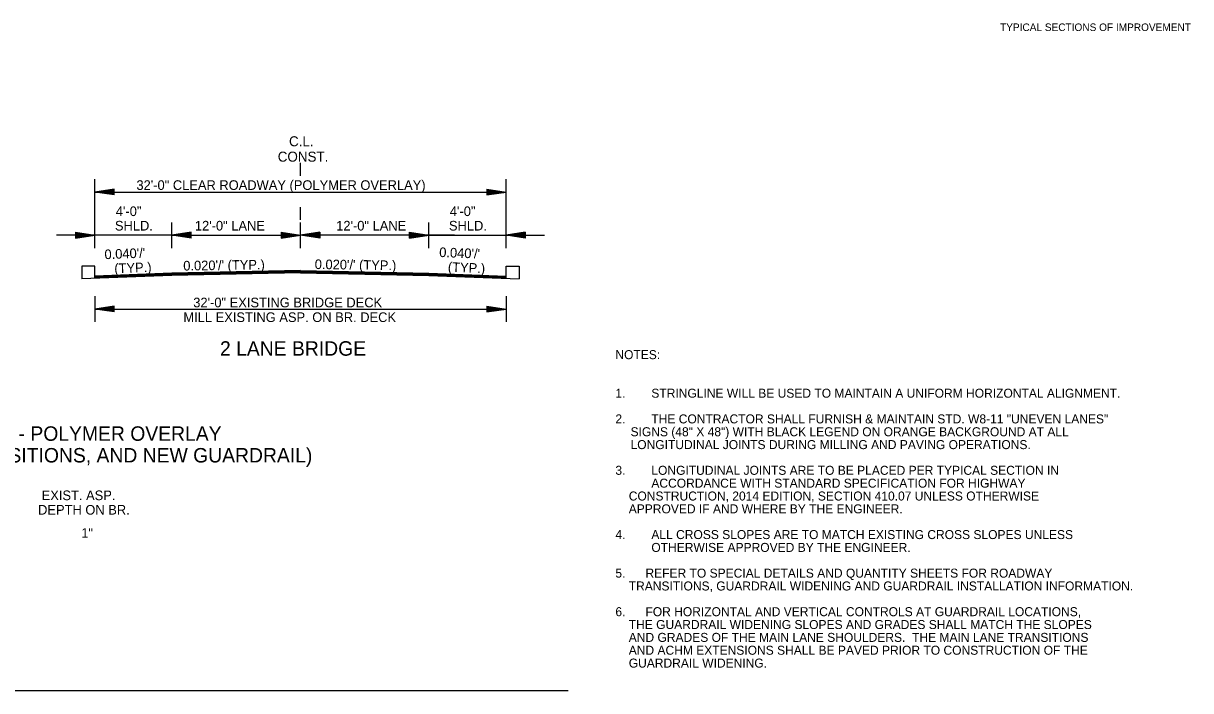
# Model space of a CAD drawing. Extents: x 545241 to 1930787, y -1971772 to 596640.
# Drawn here: x 547347 to 548255, y -1960905 to -1960386 of the extents above; entities that cross this region are included whole.
import ezdxf

# ---------------------------------------------------------------- set-up
doc = ezdxf.new("R2010")
doc.units = 0
for name, color, linetype in [('R_Border', 7, 'Continuous'), ('R_Border Notes', 7, 'Continuous'), ('R_Border Prem', 7, 'Continuous'), ('R_Draft', 7, 'Continuous')]:
    doc.layers.add(name, color=color, linetype=linetype)

msp = doc.modelspace()

# ---------------------------------------------------------------- linework, layer by layer
at = {"layer": 'R_Border'}
for p, q in [((547402.22, -1960550.83), (547372.22, -1960550.83)), ((547722.22, -1960550.83), (547752.22, -1960550.83)), ((547402.22, -1960574.9), (547392.05, -1960574.9)), ((547392.05, -1960574.9), (547392.05, -1960584.91)), ((547402.22, -1960584.51), (547402.22, -1960574.9)), ((547722.22, -1960574.93), (547732.39, -1960574.93)), ((547722.22, -1960584.34), (547722.22, -1960574.93)), ((547732.39, -1960574.93), (547732.39, -1960584.74)), ((546742.77, -1960905.24), (547770.72, -1960905.24))]:
    msp.add_line(p, q, dxfattribs=at)
at = {"layer": 'R_Draft'}
for p, q in [((547562.22, -1960504.57), (547562.22, -1960494.57)), ((547402.22, -1960560.83), (547402.22, -1960507.29)), ((547722.22, -1960560.83), (547722.22, -1960507.29)), ((547417.22, -1960515.04), (547402.22, -1960517.29)), ((547417.22, -1960515.42), (547404.72, -1960517.29)), ((547417.22, -1960515.8), (547407.3, -1960517.29)), ((547417.22, -1960516.17), (547409.8, -1960517.29)), ((547417.22, -1960516.56), (547412.34, -1960517.29)), ((547417.22, -1960519.54), (547417.22, -1960515.04)), ((547707.22, -1960515.04), (547722.22, -1960517.29)), ((547707.22, -1960515.04), (547707.22, -1960519.54)), ((547707.22, -1960515.42), (547719.71, -1960517.29)), ((547707.22, -1960515.8), (547717.13, -1960517.29)), ((547707.22, -1960516.17), (547714.64, -1960517.29)), ((547707.22, -1960516.56), (547712.09, -1960517.29)), ((547402.22, -1960517.29), (547722.22, -1960517.29)), ((547417.22, -1960519.54), (547402.22, -1960517.29)), ((547417.22, -1960519.17), (547404.72, -1960517.29)), ((547417.22, -1960518.78), (547407.3, -1960517.29)), ((547417.22, -1960518.41), (547409.8, -1960517.29)), ((547417.22, -1960518.02), (547412.34, -1960517.29)), ((547417.22, -1960516.94), (547414.85, -1960517.29)), ((547417.22, -1960517.64), (547414.85, -1960517.29)), ((547707.22, -1960516.94), (547709.59, -1960517.29)), ((547707.22, -1960519.54), (547722.22, -1960517.29)), ((547707.22, -1960518.03), (547712.09, -1960517.29)), ((547707.22, -1960518.78), (547717.13, -1960517.29)), ((547707.22, -1960519.17), (547719.71, -1960517.29)), ((547707.22, -1960518.41), (547714.64, -1960517.29)), ((547707.22, -1960517.64), (547709.59, -1960517.29)), ((547562.22, -1960538.81), (547562.22, -1960528.94)), ((547462.22, -1960560.83), (547462.22, -1960540.94)), ((547562.22, -1960560.83), (547562.22, -1960540.94)), ((547662.22, -1960560.83), (547662.22, -1960540.94)), ((547387.22, -1960548.58), (547402.22, -1960550.83)), ((547387.22, -1960548.58), (547387.22, -1960553.08)), ((547387.22, -1960548.95), (547399.71, -1960550.83)), ((547387.22, -1960549.34), (547397.13, -1960550.83)), ((547387.22, -1960549.71), (547394.64, -1960550.83)), ((547387.22, -1960550.1), (547392.09, -1960550.83)), ((547387.22, -1960550.48), (547389.59, -1960550.83)), ((547387.22, -1960553.08), (547402.22, -1960550.83)), ((547387.22, -1960551.56), (547392.09, -1960550.83)), ((547387.22, -1960552.32), (547397.13, -1960550.83)), ((547387.22, -1960552.7), (547399.71, -1960550.83)), ((547387.22, -1960551.95), (547394.64, -1960550.83)), ((547387.22, -1960551.18), (547389.59, -1960550.83)), ((547462.22, -1960550.83), (547402.22, -1960550.83)), ((547477.22, -1960548.58), (547462.22, -1960550.83)), ((547477.22, -1960553.08), (547462.22, -1960550.83)), ((547462.22, -1960550.83), (547562.22, -1960550.83)), ((547477.22, -1960548.95), (547464.72, -1960550.83)), ((547477.22, -1960552.7), (547464.72, -1960550.83)), ((547477.22, -1960549.34), (547467.3, -1960550.83)), ((547477.22, -1960552.32), (547467.3, -1960550.83)), ((547477.22, -1960549.71), (547469.8, -1960550.83)), ((547477.22, -1960551.95), (547469.8, -1960550.83)), ((547477.22, -1960550.09), (547472.34, -1960550.83)), ((547477.22, -1960551.56), (547472.34, -1960550.83)), ((547477.22, -1960550.48), (547474.85, -1960550.83)), ((547477.22, -1960551.18), (547474.85, -1960550.83)), ((547477.22, -1960553.08), (547477.22, -1960548.58)), ((547547.22, -1960548.58), (547562.22, -1960550.83)), ((547547.22, -1960548.58), (547547.22, -1960553.08)), ((547547.22, -1960548.95), (547559.71, -1960550.83)), ((547547.22, -1960549.34), (547557.13, -1960550.83)), ((547547.22, -1960549.71), (547554.64, -1960550.83)), ((547547.22, -1960550.1), (547552.09, -1960550.83)), ((547547.22, -1960550.48), (547549.59, -1960550.83)), ((547547.22, -1960553.08), (547562.22, -1960550.83)), ((547547.22, -1960551.56), (547552.09, -1960550.83)), ((547547.22, -1960552.32), (547557.13, -1960550.83)), ((547547.22, -1960552.7), (547559.71, -1960550.83)), ((547547.22, -1960551.95), (547554.64, -1960550.83)), ((547547.22, -1960551.18), (547549.59, -1960550.83)), ((547577.22, -1960548.58), (547562.22, -1960550.83)), ((547682.22, -1960550.83), (547562.22, -1960550.83)), ((547577.22, -1960553.08), (547562.22, -1960550.83)), ((547577.22, -1960548.95), (547564.72, -1960550.83)), ((547577.22, -1960552.7), (547564.72, -1960550.83)), ((547577.22, -1960549.34), (547567.3, -1960550.83)), ((547577.22, -1960552.32), (547567.3, -1960550.83)), ((547577.22, -1960549.71), (547569.8, -1960550.83)), ((547577.22, -1960551.95), (547569.8, -1960550.83)), ((547577.22, -1960550.1), (547572.34, -1960550.83)), ((547577.22, -1960551.56), (547572.34, -1960550.83)), ((547577.22, -1960550.48), (547574.85, -1960550.83)), ((547577.22, -1960551.18), (547574.85, -1960550.83)), ((547577.22, -1960548.58), (547577.22, -1960553.08)), ((547647.22, -1960548.58), (547662.22, -1960550.83)), ((547647.22, -1960553.08), (547647.22, -1960548.58)), ((547647.22, -1960548.95), (547659.71, -1960550.83)), ((547647.22, -1960549.34), (547657.13, -1960550.83)), ((547647.22, -1960549.71), (547654.64, -1960550.83)), ((547647.22, -1960550.09), (547652.09, -1960550.83)), ((547647.22, -1960550.48), (547649.59, -1960550.83)), ((547647.22, -1960553.08), (547662.22, -1960550.83)), ((547647.22, -1960551.56), (547652.09, -1960550.83)), ((547647.22, -1960552.32), (547657.13, -1960550.83)), ((547647.22, -1960552.7), (547659.71, -1960550.83)), ((547647.22, -1960551.95), (547654.64, -1960550.83)), ((547647.22, -1960551.18), (547649.59, -1960550.83)), ((547662.22, -1960550.83), (547722.22, -1960550.83)), ((547737.22, -1960548.58), (547722.22, -1960550.83)), ((547737.22, -1960553.08), (547722.22, -1960550.83)), ((547737.22, -1960548.95), (547724.72, -1960550.83)), ((547737.22, -1960552.7), (547724.72, -1960550.83)), ((547737.22, -1960549.34), (547727.3, -1960550.83)), ((547737.22, -1960552.32), (547727.3, -1960550.83)), ((547737.22, -1960549.71), (547729.8, -1960550.83)), ((547737.22, -1960551.95), (547729.8, -1960550.83)), ((547737.22, -1960550.1), (547732.34, -1960550.83)), ((547737.22, -1960551.56), (547732.34, -1960550.83)), ((547737.22, -1960550.48), (547734.85, -1960550.83)), ((547737.22, -1960551.18), (547734.85, -1960550.83)), ((547737.22, -1960548.58), (547737.22, -1960553.08)), ((547462.22, -1960580.44), (547402.22, -1960582.84)), ((547562.22, -1960578.44), (547462.22, -1960580.44)), ((547562.22, -1960578.74), (547462.22, -1960580.74)), ((547562.23, -1960579.04), (547462.22, -1960581.04)), ((547562.24, -1960579.34), (547462.22, -1960581.34)), ((547562.24, -1960579.64), (547462.22, -1960581.64)), ((547562.25, -1960579.94), (547462.22, -1960581.94)), ((547562.25, -1960580.11), (547462.22, -1960582.11)), ((547562.19, -1960579.64), (547662.22, -1960581.64)), ((547562.19, -1960579.94), (547662.22, -1960581.94)), ((547562.19, -1960580.11), (547662.22, -1960582.11)), ((547562.2, -1960579.34), (547662.22, -1960581.34)), ((547562.21, -1960578.74), (547662.22, -1960580.74)), ((547562.21, -1960579.04), (547662.22, -1960581.04)), ((547562.22, -1960578.44), (547662.22, -1960580.44)), ((547662.22, -1960580.44), (547722.22, -1960582.84)), ((547462.22, -1960582.11), (547392.05, -1960584.91)), ((547462.22, -1960580.74), (547402.22, -1960583.14)), ((547462.22, -1960581.04), (547402.22, -1960583.44)), ((547462.22, -1960581.34), (547402.22, -1960583.74)), ((547462.22, -1960581.64), (547402.22, -1960584.04)), ((547462.22, -1960581.94), (547402.22, -1960584.34)), ((547662.22, -1960580.74), (547722.22, -1960583.14)), ((547662.22, -1960581.04), (547722.22, -1960583.44)), ((547662.22, -1960581.34), (547722.22, -1960583.74)), ((547662.22, -1960581.64), (547722.22, -1960584.04)), ((547662.22, -1960581.94), (547722.22, -1960584.34)), ((547662.22, -1960582.11), (547732.39, -1960584.91)), ((547402.22, -1960598.29), (547402.22, -1960618.29)), ((547722.22, -1960598.29), (547722.22, -1960618.29)), ((547417.22, -1960606.04), (547402.22, -1960608.29)), ((547417.22, -1960606.42), (547404.72, -1960608.29)), ((547417.22, -1960606.8), (547407.3, -1960608.29)), ((547417.22, -1960607.18), (547409.8, -1960608.29)), ((547417.22, -1960607.56), (547412.34, -1960608.29)), ((547417.22, -1960610.54), (547417.22, -1960606.04)), ((547707.22, -1960606.04), (547722.22, -1960608.29)), ((547707.22, -1960606.04), (547707.22, -1960610.54)), ((547707.22, -1960606.42), (547719.71, -1960608.29)), ((547707.22, -1960606.8), (547717.13, -1960608.29)), ((547707.22, -1960607.18), (547714.64, -1960608.29)), ((547707.22, -1960607.57), (547712.09, -1960608.29)), ((547402.22, -1960608.29), (547722.22, -1960608.29)), ((547417.22, -1960610.54), (547402.22, -1960608.29)), ((547417.22, -1960610.17), (547404.72, -1960608.29)), ((547417.22, -1960609.79), (547407.3, -1960608.29)), ((547417.22, -1960609.41), (547409.8, -1960608.29)), ((547417.22, -1960609.02), (547412.34, -1960608.29)), ((547417.22, -1960607.94), (547414.85, -1960608.29)), ((547417.22, -1960608.65), (547414.85, -1960608.29)), ((547707.22, -1960607.94), (547709.59, -1960608.29)), ((547707.22, -1960610.54), (547722.22, -1960608.29)), ((547707.22, -1960609.03), (547712.09, -1960608.29)), ((547707.22, -1960609.79), (547717.13, -1960608.29)), ((547707.22, -1960610.17), (547719.71, -1960608.29)), ((547707.22, -1960609.41), (547714.64, -1960608.29)), ((547707.22, -1960608.65), (547709.59, -1960608.29))]:
    msp.add_line(p, q, dxfattribs=at)

# ---------------------------------------------------------------- texts
at = {"layer": 'R_Border Notes'}
for s, p in [('NOTES: ', (547807.36, -1960647.3)), ('1.', (547807.36, -1960677.3)), ('STRINGLINE WILL BE USED TO MAINTAIN A UNIFORM HORIZONTAL ALIGNMENT.', (547835.36, -1960677.3)), ('2.', (547807.36, -1960697.3)), ('THE CONTRACTOR SHALL FURNISH & MAINTAIN STD. W8-11 "UNEVEN LANES" ', (547835.36, -1960697.3)), ('    SIGNS (48" X 48") WITH BLACK LEGEND ON ORANGE BACKGROUND AT ALL ', (547808.76, -1960707.3)), ('    LONGITUDINAL JOINTS DURING MILLING AND PAVING OPERATIONS.', (547808.76, -1960717.3)), ('3.', (547807.36, -1960737.3)), ('LONGITUDINAL JOINTS ARE TO BE PLACED PER TYPICAL SECTION IN ', (547835.36, -1960737.3)), ('ACCORDANCE WITH STANDARD SPECIFICATION FOR HIGHWAY', (547835.36, -1960747.3)), ('    CONSTRUCTION, 2014 EDITION, SECTION 410.07 UNLESS OTHERWISE', (547807.36, -1960757.3)), ('    APPROVED IF AND WHERE BY THE ENGINEER.', (547807.36, -1960767.3)), ('4.', (547807.36, -1960787.3)), ('ALL CROSS SLOPES ARE TO MATCH EXISTING CROSS SLOPES UNLESS ', (547835.36, -1960787.3)), ('OTHERWISE APPROVED BY THE ENGINEER.', (547835.36, -1960797.3)), ('5.      REFER TO SPECIAL DETAILS AND QUANTITY SHEETS FOR ROADWAY', (547807.36, -1960817.3)), ('    TRANSITIONS, GUARDRAIL WIDENING AND GUARDRAIL INSTALLATION INFORMATION.', (547807.36, -1960827.3)), ('6.      FOR HORIZONTAL AND VERTICAL CONTROLS AT GUARDRAIL LOCATIONS,', (547807.36, -1960847.3)), ('    THE GUARDRAIL WIDENING SLOPES AND GRADES SHALL MATCH THE SLOPES', (547807.36, -1960857.3)), ('    AND GRADES OF THE MAIN LANE SHOULDERS.  THE MAIN LANE TRANSITIONS', (547807.36, -1960867.3)), ('    AND ACHM EXTENSIONS SHALL BE PAVED PRIOR TO CONSTRUCTION OF THE', (547807.36, -1960877.3)), ('    GUARDRAIL WIDENING.', (547807.36, -1960887.3))]:
    msp.add_text(s, height=7, dxfattribs=at).set_placement(p)
at = {"layer": 'R_Border Prem'}
msp.add_text('TYPICAL SECTIONS OF IMPROVEMENT', height=5.862, rotation=360, dxfattribs=at).set_placement((548106.81, -1960391.97))
at = {"layer": 'R_Draft'}
for s, height, p in [('C.L.', 7.8, (547553.32, -1960481.68)), ('CONST.', 7.8, (547544.54, -1960493.64)), ('32\'-0" CLEAR ROADWAY (POLYMER OVERLAY)', 7.5, (547434.54, -1960515.62)), ('4\'-0" ', 7.5, (547418.49, -1960535.97)), ('4\'-0"', 7.5, (547678.49, -1960535.97)), ('SHLD.', 7.5, (547417.81, -1960547.22)), ('12\'-0" LANE', 7.5, (547480.03, -1960547.22)), ('12\'-0" LANE', 7.5, (547590.03, -1960547.22)), ('SHLD.', 7.5, (547677.81, -1960547.22)), ('32\'-0" EXISTING BRIDGE DECK', 7.5, (547478.77, -1960606.97)), ('MILL EXISTING ASP. ON BR. DECK', 7.5, (547471.1, -1960618.41)), ('2 LANE BRIDGE', 11.25, (547499.59, -1960644.61)), ('32 FT. CLEAR ROADWAY BRIDGE - POLYMER OVERLAY', 11.25, (547097.04, -1960710.84)), ('(MILLING ON BR. DECK, ROADWAY TRANSITIONS, AND NEW GUARDRAIL)', 11.25, (547036.54, -1960727.71)), (' EXIST. ASP. ', 7.5, (547358, -1960757.02)), ('DEPTH ON BR. ', 7.5, (547358, -1960768.27)), (' 1"', 7.5, (547388.83, -1960786.32))]:
    msp.add_text(s, height=height, dxfattribs=at).set_placement(p)
for s, rotation, p in [("0.040'/' ", 2.29061, (547409.82, -1960569.56)), ("0.040'/' ", 357.70939, (547670.12, -1960567.78)), ("0.020'/' (TYP.)", 0.87191, (547471.05, -1960578.39)), ("0.020'/' (TYP.)", 359.12809, (547573.29, -1960577.16)), ('(TYP.)', 2.29061, (547417.47, -1960580.52)), ('(TYP.)', 357.70939, (547676.87, -1960579.31))]:
    msp.add_text(s, height=7.5, rotation=rotation, dxfattribs=at).set_placement(p)

doc.saveas('drawing.dxf')
